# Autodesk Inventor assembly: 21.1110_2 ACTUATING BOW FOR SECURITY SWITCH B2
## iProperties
Created: 2007-05
Part Number: 21.1110_2 ACTUATING BOW FOR SECURITY SWITCH B2
Document SubType Name: Assembly
Designer: Andy Moles
Author: Andy Moles
